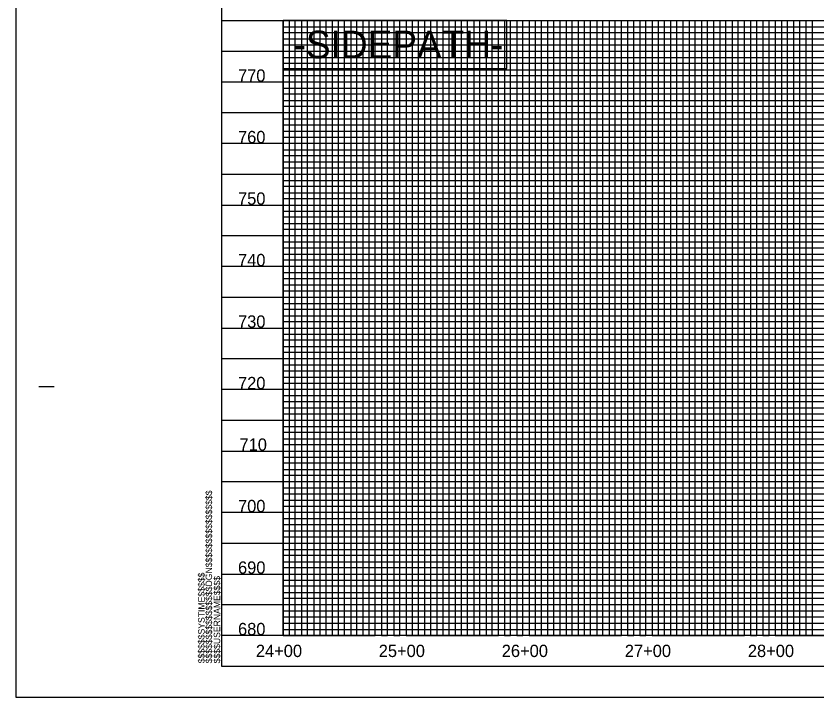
# Model space of a CAD drawing. Extents: x 1524869 to 1526553, y 501099 to 502199.
# Drawn here: x 1524869 to 1525519, y 501099 to 501652 of the extents above; entities that cross this region are included whole.
import ezdxf

# ---------------------------------------------------------------- set-up
doc = ezdxf.new("R2010")
doc.units = 0
for name, color, linetype in [('Exist Vertical Profile Horizontal Axis Label Major', 7, 'Continuous'), ('Exist Vertical Profile Vertical Axis Label', 7, 'Continuous'), ('Prop Grid Mask', 7, 'Continuous'), ('Prop Horizontal Alignment Curve and Spiral Data', 7, 'Continuous'), ('Sheet Layout Profile Border Port 2', 7, 'Continuous'), ('Sheet Plot Border Outside CELL', 7, 'Continuous'), ('Sheet Profile CELL', 7, 'Continuous'), ('Sheet Profile Grid Major CELL', 7, 'Continuous'), ('Sheet Profile Grid Middle CELL', 7, 'Continuous'), ('Sheet Profile Grid Minor CELL', 7, 'Continuous')]:
    doc.layers.add(name, color=color, linetype=linetype)

msp = doc.modelspace()

# ---------------------------------------------------------------- linework, layer by layer
at = {"layer": 'Prop Grid Mask'}
msp.add_lwpolyline([(1525086.08, 501609.52), (1525267.99, 501609.52), (1525267.99, 501648.56), (1525086.08, 501648.56)], close=True, dxfattribs=at)
at = {"layer": 'Sheet Layout Profile Border Port 2'}
msp.add_lwpolyline([(1525086.08, 501648.56), (1526486.08, 501648.56), (1526486.08, 501148.56), (1525086.08, 501148.56)], close=True, dxfattribs=at)
at = {"layer": 'Sheet Plot Border Outside CELL'}
msp.add_lwpolyline([(1524869.08, 501098.56), (1526553.08, 501098.56), (1526553.08, 502198.56), (1524869.08, 502198.56)], close=True, dxfattribs=at)
at = {"layer": 'Sheet Profile CELL'}
for p, q in [((1525036.08, 501648.56), (1526536.08, 501648.56)), ((1524887.58, 501351.06), (1524900.08, 501351.06)), ((1526536.08, 501148.56), (1525036.08, 501148.56)), ((1525036.08, 501123.56), (1526536.08, 501123.56)), ((1525036.08, 501123.56), (1525036.08, 501123.56)), ((1525036.08, 501123.56), (1525036.08, 501123.56)), ((1525036.08, 501123.56), (1525036.08, 501123.56)), ((1525036.08, 501123.56), (1525036.08, 501123.56)), ((1525036.08, 501123.56), (1525036.08, 501123.56)), ((1525036.08, 501123.56), (1525036.08, 501123.56)), ((1525036.08, 501123.56), (1525036.08, 501123.56))]:
    msp.add_line(p, q, dxfattribs=at)
msp.add_lwpolyline([(1526536.08, 502173.56), (1525036.08, 502173.56), (1525036.08, 501123.56), (1526536.08, 501123.56)], close=True, dxfattribs=at)
msp.add_lwpolyline([(1525073.58, 501123.56), (1525073.58, 501123.56)], dxfattribs=at)
at = {"layer": 'Sheet Profile Grid Major CELL'}
msp.add_line((1525036.08, 501148.56), (1525036.08, 501148.56), dxfattribs=at)
for points in [[(1525086.08, 501648.56), (1525086.08, 501148.56), (1525136.08, 501148.56), (1525136.08, 501648.56), (1525186.08, 501648.56), (1525186.08, 501148.56), (1525236.08, 501148.56), (1525236.08, 501648.56), (1525286.08, 501648.56), (1525286.08, 501148.56), (1525336.08, 501148.56), (1525336.08, 501648.56), (1525386.08, 501648.56), (1525386.08, 501148.56), (1525436.08, 501148.56), (1525436.08, 501648.56), (1525486.08, 501648.56), (1525486.08, 501148.56), (1525536.08, 501148.56)], [(1526536.08, 501598.56), (1525036.08, 501598.56)], [(1526536.08, 501548.56), (1525036.08, 501548.56), (1525036.08, 501498.56), (1526536.08, 501498.56)], [(1526536.08, 501448.56), (1525036.08, 501448.56), (1525036.08, 501398.56), (1526536.08, 501398.56)], [(1526536.08, 501348.56), (1525036.08, 501348.56), (1525036.08, 501298.56), (1526536.08, 501298.56)], [(1526536.08, 501248.56), (1525036.08, 501248.56), (1525036.08, 501248.56), (1525036.08, 501198.56), (1526536.08, 501198.56)], [(1526536.08, 501148.56), (1525036.08, 501148.56)]]:
    msp.add_lwpolyline(points, dxfattribs=at)
at = {"layer": 'Sheet Profile Grid Middle CELL'}
for points in [[(1525061.08, 501648.56), (1525111.08, 501648.56), (1525111.08, 501148.56), (1525161.08, 501148.56), (1525161.08, 501648.56), (1525211.08, 501648.56), (1525211.08, 501148.56), (1525261.08, 501148.56), (1525261.08, 501648.56), (1525311.08, 501648.56), (1525311.08, 501148.56), (1525361.08, 501148.56), (1525361.08, 501648.56), (1525411.08, 501648.56), (1525411.08, 501148.56), (1525461.08, 501148.56), (1525461.08, 501648.56), (1525511.08, 501648.56), (1525511.08, 501148.56), (1525561.08, 501148.56)], [(1525036.08, 501623.56), (1526536.08, 501623.56)], [(1526536.08, 501573.56), (1525036.08, 501573.56), (1525036.08, 501523.56), (1526536.08, 501523.56)], [(1526536.08, 501473.56), (1525036.08, 501473.56), (1525036.08, 501423.56), (1526536.08, 501423.56)], [(1526536.08, 501373.56), (1525036.08, 501373.56), (1525036.08, 501323.56), (1526536.08, 501323.56)], [(1526536.08, 501273.56), (1525036.08, 501273.56), (1525036.08, 501223.56), (1526536.08, 501223.56)], [(1526536.08, 501173.56), (1525036.08, 501173.56)]]:
    msp.add_lwpolyline(points, dxfattribs=at)
at = {"layer": 'Sheet Profile Grid Minor CELL'}
for p, q in [((1525086.08, 501643.56), (1526486.08, 501643.56)), ((1526486.08, 501638.56), (1525086.08, 501638.56)), ((1525086.08, 501638.56), (1525086.08, 501638.56)), ((1525086.08, 501638.56), (1525086.08, 501638.56)), ((1525086.08, 501633.56), (1526486.08, 501633.56)), ((1526486.08, 501628.56), (1525086.08, 501628.56)), ((1525086.08, 501618.56), (1526486.08, 501618.56)), ((1526486.08, 501613.56), (1525086.08, 501613.56)), ((1525086.08, 501608.56), (1526486.08, 501608.56)), ((1526486.08, 501603.56), (1525086.08, 501603.56)), ((1525086.08, 501593.56), (1526486.08, 501593.56)), ((1526486.08, 501588.56), (1525086.08, 501588.56)), ((1525086.08, 501583.56), (1526486.08, 501583.56)), ((1526486.08, 501578.56), (1525086.08, 501578.56)), ((1525086.08, 501568.56), (1526486.08, 501568.56)), ((1526486.08, 501563.56), (1525086.08, 501563.56)), ((1525086.08, 501558.56), (1526486.08, 501558.56)), ((1526486.08, 501553.56), (1525086.08, 501553.56)), ((1525086.08, 501543.56), (1526486.08, 501543.56)), ((1526486.08, 501538.56), (1525086.08, 501538.56)), ((1525086.08, 501533.56), (1526486.08, 501533.56)), ((1526486.08, 501528.56), (1525086.08, 501528.56)), ((1525086.08, 501518.56), (1526486.08, 501518.56)), ((1526486.08, 501513.56), (1525086.08, 501513.56)), ((1525086.08, 501508.56), (1526486.08, 501508.56)), ((1526486.08, 501503.56), (1525086.08, 501503.56)), ((1525086.08, 501493.56), (1526486.08, 501493.56)), ((1526486.08, 501488.56), (1525086.08, 501488.56)), ((1525086.08, 501483.56), (1526486.08, 501483.56)), ((1526486.08, 501478.56), (1525086.08, 501478.56)), ((1525086.08, 501468.56), (1526486.08, 501468.56)), ((1526486.08, 501463.56), (1525086.08, 501463.56)), ((1525086.08, 501458.56), (1526486.08, 501458.56)), ((1526486.08, 501453.56), (1525086.08, 501453.71)), ((1525086.08, 501443.56), (1526486.08, 501443.56)), ((1526486.08, 501438.56), (1525086.08, 501438.56)), ((1525086.08, 501433.56), (1526486.08, 501433.56)), ((1526486.08, 501428.56), (1525086.08, 501428.56)), ((1525086.08, 501418.56), (1526486.08, 501418.56)), ((1526486.08, 501413.56), (1525086.08, 501413.56)), ((1525086.08, 501408.56), (1526486.08, 501408.56)), ((1526486.08, 501403.56), (1525086.08, 501403.56)), ((1525086.08, 501393.56), (1526486.08, 501393.56)), ((1526486.08, 501388.56), (1525086.08, 501388.56)), ((1525086.08, 501383.56), (1526486.08, 501383.56)), ((1526486.08, 501378.56), (1525086.08, 501378.56)), ((1525086.08, 501368.56), (1526486.08, 501368.56)), ((1526486.08, 501363.56), (1525086.08, 501363.56)), ((1525086.08, 501358.56), (1526486.08, 501358.56)), ((1526486.08, 501353.56), (1525086.08, 501353.56)), ((1525086.08, 501343.56), (1526486.08, 501343.56)), ((1526486.08, 501338.56), (1525086.08, 501338.56)), ((1525086.08, 501333.56), (1526486.08, 501333.56)), ((1526486.08, 501328.56), (1525086.08, 501328.56)), ((1525086.08, 501318.56), (1526486.08, 501318.56)), ((1526486.08, 501313.56), (1525086.08, 501313.56)), ((1525086.08, 501308.56), (1526486.08, 501308.56)), ((1526486.08, 501303.56), (1525086.08, 501303.56)), ((1525086.08, 501293.56), (1526486.08, 501293.56)), ((1526486.08, 501288.56), (1525086.08, 501288.56)), ((1525086.08, 501283.56), (1526486.08, 501283.56)), ((1526486.08, 501278.56), (1525086.08, 501278.56)), ((1525086.08, 501268.56), (1526486.08, 501268.56)), ((1526486.08, 501263.56), (1525086.08, 501263.56)), ((1525086.08, 501258.56), (1526486.08, 501258.56)), ((1526486.08, 501253.56), (1525086.08, 501253.56)), ((1525086.08, 501243.56), (1526486.08, 501243.56)), ((1526486.08, 501238.56), (1525086.08, 501238.56)), ((1525086.08, 501233.56), (1526486.08, 501233.56)), ((1526486.08, 501228.56), (1525086.08, 501228.56)), ((1525086.08, 501218.56), (1526486.08, 501218.56)), ((1526486.08, 501213.56), (1525086.08, 501213.56)), ((1525086.08, 501208.56), (1526486.08, 501208.56)), ((1526486.08, 501203.56), (1525086.08, 501203.56)), ((1525086.08, 501193.56), (1526486.08, 501193.56)), ((1526486.08, 501188.56), (1525086.08, 501188.56)), ((1525086.08, 501183.56), (1526486.08, 501183.56)), ((1526486.08, 501178.56), (1525086.08, 501178.56)), ((1525086.08, 501168.56), (1526486.08, 501168.56)), ((1526486.08, 501163.56), (1525086.08, 501163.56)), ((1525086.08, 501158.56), (1526486.08, 501158.56)), ((1525086.08, 501153.56), (1526486.08, 501153.56))]:
    msp.add_line(p, q, dxfattribs=at)
for points in [[(1525086.08, 501648.56), (1525091.08, 501648.56), (1525091.08, 501148.56), (1525096.08, 501148.56), (1525096.08, 501648.56), (1525101.08, 501648.56), (1525101.08, 501148.56), (1525106.08, 501148.56), (1525106.08, 501648.56), (1525116.08, 501648.56), (1525116.08, 501148.56), (1525121.08, 501148.56), (1525121.08, 501648.56), (1525126.08, 501648.56), (1525126.08, 501148.56), (1525131.08, 501148.56), (1525141.08, 501148.56), (1525146.08, 501148.56), (1525146.08, 501648.56), (1525151.08, 501648.56), (1525151.08, 501148.56), (1525156.08, 501148.56), (1525156.08, 501648.56), (1525166.08, 501648.56), (1525166.08, 501148.56), (1525171.08, 501148.56), (1525171.08, 501648.56), (1525176.08, 501648.56), (1525176.08, 501148.56), (1525181.08, 501148.56), (1525181.08, 501648.56), (1525191.08, 501648.56), (1525191.08, 501148.56), (1525196.08, 501148.56), (1525196.08, 501648.56), (1525201.08, 501648.56), (1525201.08, 501148.56), (1525206.08, 501148.56), (1525206.08, 501648.56), (1525216.08, 501648.56), (1525216.08, 501148.56), (1525221.08, 501148.56), (1525221.08, 501648.56), (1525226.08, 501648.56), (1525226.08, 501148.56), (1525231.08, 501148.56), (1525231.08, 501648.56), (1525241.08, 501648.56), (1525241.08, 501148.56), (1525246.08, 501148.56), (1525246.08, 501648.56), (1525251.08, 501648.56), (1525251.08, 501148.56), (1525256.08, 501148.56), (1525256.08, 501648.56), (1525266.08, 501648.56), (1525266.08, 501148.56), (1525271.08, 501148.56), (1525271.08, 501648.56), (1525276.08, 501648.56), (1525276.08, 501148.56), (1525281.08, 501148.56), (1525281.08, 501648.56), (1525291.08, 501648.56), (1525291.08, 501148.56), (1525296.08, 501148.56), (1525296.08, 501648.56), (1525301.08, 501648.56), (1525301.08, 501148.56)], [(1525131.08, 501148.56), (1525131.08, 501648.56), (1525141.08, 501648.56), (1525141.08, 501148.56)], [(1525301.08, 501148.56), (1525306.08, 501148.56), (1525306.08, 501648.56), (1525316.08, 501648.56), (1525316.08, 501148.56), (1525321.08, 501148.56), (1525321.08, 501648.56), (1525326.08, 501648.56), (1525326.08, 501148.56), (1525331.08, 501148.56), (1525331.08, 501648.56), (1525341.08, 501648.56), (1525341.08, 501148.56), (1525346.08, 501148.56), (1525346.08, 501648.56), (1525351.08, 501648.56), (1525351.08, 501148.56), (1525356.08, 501148.56), (1525356.08, 501648.56), (1525366.08, 501648.56), (1525366.08, 501148.56), (1525371.08, 501148.56), (1525371.08, 501648.56), (1525376.08, 501648.56), (1525376.08, 501148.56), (1525381.08, 501148.56), (1525381.08, 501648.56), (1525391.08, 501648.56), (1525391.08, 501148.56), (1525396.08, 501148.56), (1525396.08, 501648.56), (1525401.08, 501648.56), (1525401.08, 501148.56), (1525406.08, 501148.56), (1525406.08, 501648.56), (1525416.08, 501648.56), (1525416.08, 501148.56), (1525421.08, 501148.56), (1525421.08, 501648.56), (1525426.08, 501648.56), (1525426.08, 501148.56), (1525431.08, 501148.56), (1525431.08, 501648.56), (1525441.08, 501648.56), (1525441.08, 501148.56), (1525446.08, 501148.56), (1525446.08, 501648.56), (1525451.08, 501648.56), (1525451.08, 501148.56), (1525456.08, 501148.56), (1525456.08, 501648.56), (1525466.08, 501648.56), (1525466.08, 501148.56), (1525471.08, 501148.56), (1525471.08, 501648.56), (1525476.08, 501648.56), (1525476.08, 501148.56), (1525481.08, 501148.56), (1525481.08, 501648.56), (1525491.08, 501648.56), (1525491.08, 501148.56), (1525496.08, 501148.56), (1525496.08, 501648.56), (1525501.08, 501648.56), (1525501.08, 501148.56), (1525506.08, 501148.56), (1525506.08, 501648.56), (1525516.08, 501648.56), (1525516.08, 501148.56), (1525521.08, 501148.56)]]:
    msp.add_lwpolyline(points, dxfattribs=at)

# ---------------------------------------------------------------- texts
at = {"layer": 'Exist Vertical Profile Horizontal Axis Label Major'}
for s, p in [('24+00', (1525064.01, 501131.06)), ('25+00', (1525163.87, 501131.06)), ('26+00', (1525263.85, 501131.06)), ('27+00', (1525363.85, 501131.06)), ('28+00', (1525463.85, 501131.06))]:
    msp.add_text(s, height=10, dxfattribs=at).set_placement(p)
at = {"layer": 'Exist Vertical Profile Vertical Axis Label'}
for s, p in [('770', (1525049.51, 501598.81)), ('760', (1525049.51, 501548.81)), ('750', (1525049.51, 501498.81)), ('740', (1525049.51, 501448.81)), ('730', (1525049.51, 501398.81)), ('720', (1525049.51, 501348.81)), ('710', (1525050.71, 501298.81)), ('700', (1525049.51, 501248.81)), ('690', (1525049.51, 501198.81)), ('680', (1525049.51, 501148.81))]:
    msp.add_text(s, height=10, dxfattribs=at).set_placement(p)
at = {"layer": 'Prop Horizontal Alignment Curve and Spiral Data'}
msp.add_text('-SIDEPATH-', height=22.5, rotation=360, dxfattribs=at).set_placement((1525094.68, 501617.79))
at = {"layer": 'Sheet Profile CELL'}
for s, p in [('$$$$$$$$$$$$$$$$DGN$$$$$$$$$$$$$$$$', (1525028.44, 501125.94)), ('$$$$$$SYSTIME$$$$$', (1525022.39, 501125.94)), ('$$$$USERNAME$$$$', (1525035.02, 501125.95))]:
    msp.add_text(s, height=5.25, rotation=90, dxfattribs=at).set_placement(p)

doc.saveas('drawing.dxf')
